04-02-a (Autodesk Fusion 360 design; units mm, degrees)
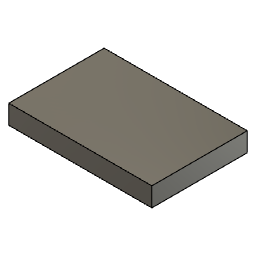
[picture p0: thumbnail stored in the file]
sketch "スケッチ" plane through (0, 0, 0) normal (0, 1, 0) x axis (1, 0, 0)
  line L1 (-15, 10) -> (15, 10)
  line L2 (-15, -10) -> (-15, 10)
  line L3 (15, -10) -> (-15, -10)
  line L4 (15, 10) -> (15, -10)
  line L5 (-15, -10) -> (15, 10)
  line L6 (15, -10) -> (-15, 10)
  point P6 (0, 0)
  point P1 (0, 0)
  point P2 (15, 10)
  point P3 (-15, 10)
  point P5 (15, -10)
  horizontal L1
  perpendicular L1 L2
  parallel L1 L3
  parallel L2 L4
  coincident L5 P6
  coincident L6 P6
  coincident P1 P6
  dimension "d5" distance P2 P3 = 30
  dimension "d6" distance P2 P5 = 20
extrude "押し出し" new body sketch "スケッチ" profile of L1 L2 L3 L4 along normal blind 4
